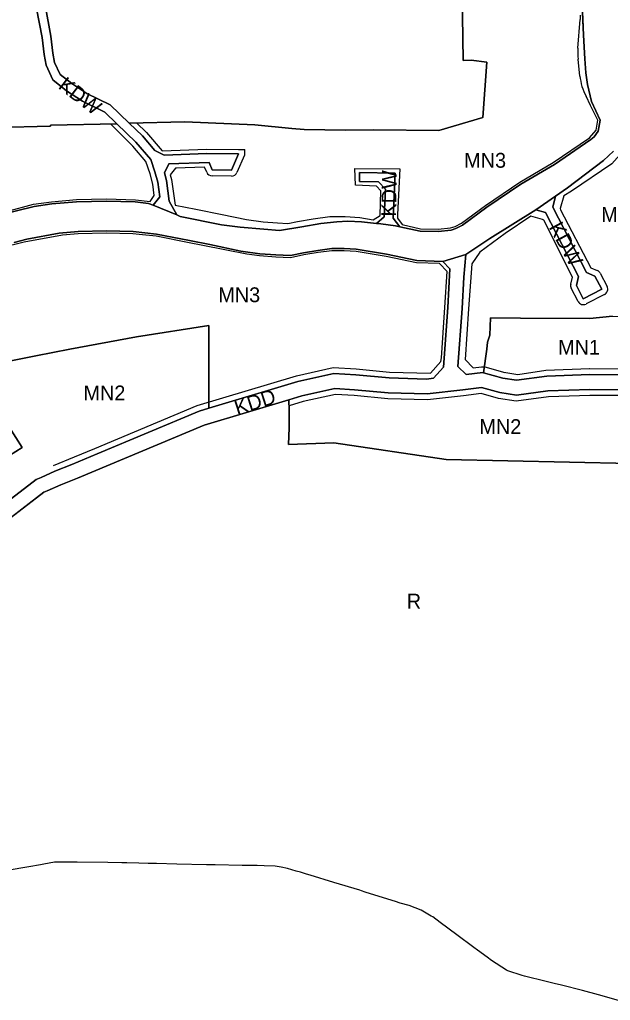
# Model space of a CAD drawing. Extents: x 7417187 to 7419415, y 5539178 to 5540826.
# Drawn here: x 7417830 to 7418229, y 5539345 to 5540006 of the extents above; entities that cross this region are included whole.
import ezdxf

# ---------------------------------------------------------------- set-up
doc = ezdxf.new("R2010")
doc.units = 0
for name, color, linetype in [('linie_rozgraniczajace', 7, 'Continuous'), ('linie_zabudowy_nieprzekraczalne', 7, 'Continuous'), ('oznaczenia_przeznaczen', 7, 'Continuous')]:
    doc.layers.add(name, color=color, linetype=linetype)

msp = doc.modelspace()

# ---------------------------------------------------------------- linework, layer by layer
at = {"layer": 'linie_rozgraniczajace'}
for p, q in [((7418210.59, 5539995.36), (7418209.09, 5540027.1)), ((7417841.94, 5540013.34), (7417845.64, 5539993.82)), ((7417845.64, 5539993.82), (7417846.97, 5539982.25)), ((7418211.34, 5539979.47), (7418210.59, 5539995.36)), ((7417846.97, 5539982.25), (7417848.33, 5539975.12)), ((7418212.06, 5539969.99), (7418211.34, 5539979.47)), ((7417848.33, 5539975.12), (7417852.9, 5539965.11)), ((7418213.25, 5539962.01), (7418212.06, 5539969.99)), ((7417852.9, 5539965.11), (7417862.11, 5539957.8)), ((7418215.88, 5539950.72), (7418213.25, 5539962.01)), ((7417862.11, 5539957.8), (7417872.83, 5539950.87)), ((7417872.83, 5539950.87), (7417887.96, 5539943.47)), ((7418221.87, 5539938.02), (7418215.88, 5539950.72)), ((7417887.96, 5539943.47), (7417896.06, 5539935.67)), ((7417810.61, 5539933.08), (7417851.22, 5539934.03)), ((7417851.22, 5539934.03), (7417810.61, 5539933.08)), ((7417851.18, 5539934.74), (7417896.06, 5539935.67)), ((7417896.06, 5539935.67), (7417851.18, 5539934.74)), ((7417851.22, 5539934.03), (7417851.18, 5539934.74)), ((7417851.18, 5539934.74), (7417851.22, 5539934.03)), ((7417896.06, 5539935.67), (7417908.89, 5539923.32)), ((7418220.53, 5539930.56), (7418221.87, 5539938.02)), ((7418215.47, 5539925.07), (7418217.77, 5539926.8)), ((7418217.77, 5539926.8), (7418220.53, 5539930.56)), ((7417908.89, 5539923.32), (7417918.86, 5539911.61)), ((7418190.95, 5539908.26), (7418215.47, 5539925.07)), ((7418230.77, 5539917.17), (7418223.92, 5539910.78)), ((7417918.86, 5539911.61), (7417921.67, 5539903.35)), ((7418168.34, 5539894.94), (7418190.95, 5539908.26)), ((7418223.92, 5539910.78), (7418199.71, 5539892.43)), ((7417921.67, 5539903.35), (7417923.53, 5539896.24)), ((7417923.53, 5539896.24), (7417924.87, 5539886.44)), ((7418145.38, 5539879.33), (7418168.34, 5539894.94)), ((7417924.87, 5539886.44), (7417920.45, 5539880.67)), ((7418191.59, 5539886.77), (7418178.38, 5539877.62)), ((7418199.71, 5539892.43), (7418191.59, 5539886.77)), ((7417840.17, 5539879.93), (7417802.91, 5539870.7)), ((7417802.91, 5539870.7), (7417840.17, 5539879.93)), ((7417852.11, 5539881.6), (7417840.17, 5539879.93)), ((7417840.17, 5539879.93), (7417852.11, 5539881.6)), ((7417868.87, 5539883.03), (7417852.11, 5539881.6)), ((7417852.11, 5539881.6), (7417868.87, 5539883.03)), ((7417889.12, 5539883.48), (7417868.87, 5539883.03)), ((7417868.87, 5539883.03), (7417889.12, 5539883.48)), ((7417908.45, 5539882.94), (7417889.12, 5539883.48)), ((7417889.12, 5539883.48), (7417908.45, 5539882.94)), ((7417917.24, 5539881.98), (7417908.45, 5539882.94)), ((7417908.45, 5539882.94), (7417917.24, 5539881.98)), ((7417920.45, 5539880.67), (7417917.24, 5539881.98)), ((7417917.24, 5539881.98), (7417920.45, 5539880.67)), ((7417920.45, 5539880.67), (7417936.35, 5539874.16)), ((7418129.07, 5539867.36), (7418145.38, 5539879.33)), ((7417936.35, 5539874.16), (7417938.72, 5539873.19)), ((7417938.72, 5539873.19), (7417966.51, 5539867.57)), ((7418178.38, 5539877.62), (7418147.41, 5539858.29)), ((7417966.51, 5539867.57), (7417979.02, 5539865.96)), ((7418005.58, 5539863.75), (7418020.68, 5539866.09)), ((7418020.68, 5539866.09), (7418033.43, 5539868.33)), ((7418033.43, 5539868.33), (7418044.19, 5539869.55)), ((7418044.19, 5539869.55), (7418051.69, 5539870.01)), ((7418051.69, 5539870.01), (7418060.94, 5539869.6)), ((7418060.94, 5539869.6), (7418070.99, 5539868.49)), ((7418070.99, 5539868.49), (7418073.97, 5539868.16)), ((7418073.97, 5539868.16), (7418083.89, 5539866.83)), ((7418083.89, 5539866.83), (7418086.85, 5539866.21)), ((7418086.85, 5539866.21), (7418100.5, 5539863.34)), ((7418124.58, 5539865.09), (7418129.07, 5539867.36)), ((7417857.1, 5539861.95), (7417835.32, 5539857.93)), ((7417869.95, 5539863.05), (7417857.1, 5539861.95)), ((7417889.06, 5539863.47), (7417869.95, 5539863.05)), ((7417906.99, 5539862.97), (7417889.06, 5539863.47)), ((7417922.74, 5539861.35), (7417906.99, 5539862.97)), ((7417945.07, 5539856.9), (7417922.74, 5539861.35)), ((7417979.02, 5539865.96), (7417995.05, 5539864.58)), ((7417995.05, 5539864.58), (7418005.58, 5539863.75)), ((7418100.5, 5539863.34), (7418112.6, 5539863.03)), ((7418112.6, 5539863.03), (7418121.24, 5539863.99)), ((7418121.24, 5539863.99), (7418124.58, 5539865.09)), ((7417835.32, 5539857.93), (7417826.89, 5539855.67)), ((7417958.72, 5539854.27), (7417945.07, 5539856.9)), ((7417979.67, 5539849.86), (7417958.72, 5539854.27)), ((7418147.41, 5539858.29), (7418131.18, 5539847.53)), ((7417992.31, 5539848.05), (7417979.67, 5539849.86)), ((7418003.21, 5539847.35), (7417992.31, 5539848.05)), ((7418012.95, 5539846.9), (7418003.21, 5539847.35)), ((7418021.79, 5539848.71), (7418012.95, 5539846.9)), ((7418031.39, 5539850.33), (7418021.79, 5539848.71)), ((7418040.91, 5539851.55), (7418031.39, 5539850.33)), ((7418049.26, 5539851.57), (7418040.91, 5539851.55)), ((7418057.39, 5539851.07), (7418049.26, 5539851.57)), ((7418077.8, 5539847.67), (7418057.39, 5539851.07)), ((7418098.17, 5539843.4), (7418077.8, 5539847.67)), ((7418131.18, 5539847.53), (7418115.79, 5539842.94)), ((7418115.79, 5539842.94), (7418098.17, 5539843.4)), ((7417954.87, 5539732.61), (7418011.89, 5539749.7)), ((7418011.89, 5539749.7), (7418012.17, 5539742.43)), ((7418012.17, 5539742.43), (7418012.2, 5539730.83)), ((7417869.58, 5539696.91), (7417954.87, 5539732.61)), ((7418012.2, 5539730.83), (7418011.72, 5539719.57)), ((7418011.72, 5539719.57), (7418042.23, 5539720.7)), ((7418042.23, 5539720.7), (7418117.97, 5539709.49)), ((7418117.97, 5539709.49), (7418242.64, 5539706.65)), ((7417858.2, 5539692.46), (7417869.58, 5539696.91)), ((7417846.75, 5539687.32), (7417848.94, 5539688.24)), ((7417848.94, 5539688.24), (7417858.2, 5539692.46)), ((7417810.02, 5539659.15), (7417846.75, 5539687.32)), ((7417846.77, 5539436.79), (7417844.56, 5539436.33)), ((7417853.93, 5539438.26), (7417846.77, 5539436.79)), ((7417866.11, 5539438.22), (7417853.93, 5539438.26)), ((7417869.17, 5539438.17), (7417866.11, 5539438.22)), ((7417889.97, 5539437.85), (7417869.17, 5539438.17)), ((7417899.27, 5539437.7), (7417889.97, 5539437.85)), ((7417902.78, 5539437.63), (7417899.27, 5539437.7)), ((7417910.78, 5539437.47), (7417902.78, 5539437.63)), ((7417917.14, 5539437.34), (7417910.78, 5539437.47)), ((7417922.8, 5539437.23), (7417917.14, 5539437.34)), ((7417936.55, 5539436.91), (7417922.8, 5539437.23)), ((7417956.45, 5539436.46), (7417936.55, 5539436.91)), ((7417835.28, 5539434.72), (7417823.32, 5539432.65)), ((7417836.64, 5539434.96), (7417835.28, 5539434.72)), ((7417844.56, 5539436.33), (7417836.64, 5539434.96)), ((7417962.17, 5539436.33), (7417956.45, 5539436.46)), ((7417980.49, 5539436.01), (7417962.17, 5539436.33)), ((7417989.19, 5539435.85), (7417980.49, 5539436.01)), ((7417990.59, 5539435.82), (7417989.19, 5539435.85)), ((7417995.25, 5539435.73), (7417990.59, 5539435.82)), ((7418002.69, 5539435.5), (7417995.25, 5539435.73)), ((7418006.65, 5539434.7), (7418002.69, 5539435.5)), ((7418010.93, 5539433.83), (7418006.65, 5539434.7)), ((7418016.85, 5539432.18), (7418010.93, 5539433.83)), ((7418019.77, 5539431.37), (7418016.85, 5539432.18)), ((7418023.93, 5539430.1), (7418019.77, 5539431.37)), ((7418026.23, 5539429.4), (7418023.93, 5539430.1)), ((7418042.16, 5539424.55), (7418026.23, 5539429.4)), ((7418059.77, 5539419.19), (7418042.16, 5539424.55)), ((7418060.83, 5539418.87), (7418059.77, 5539419.19)), ((7418063.4, 5539418.05), (7418060.83, 5539418.87)), ((7418075.83, 5539414.1), (7418063.4, 5539418.05)), ((7418083.78, 5539411.57), (7418075.83, 5539414.1)), ((7418087.03, 5539410.64), (7418083.78, 5539411.57)), ((7418093.11, 5539408.89), (7418087.03, 5539410.64)), ((7418101.11, 5539405.89), (7418093.11, 5539408.89)), ((7418107.79, 5539401.88), (7418101.11, 5539405.89)), ((7418108.88, 5539401.24), (7418107.79, 5539401.88)), ((7418114.02, 5539397.42), (7418108.88, 5539401.24)), ((7418125.14, 5539389.19), (7418114.02, 5539397.42)), ((7418136.55, 5539380.72), (7418125.14, 5539389.19)), ((7418138.99, 5539378.92), (7418136.55, 5539380.72)), ((7418145.62, 5539374.05), (7418138.99, 5539378.92)), ((7418148.55, 5539371.9), (7418145.62, 5539374.05)), ((7418158.55, 5539365.49), (7418148.55, 5539371.9)), ((7418159.45, 5539364.92), (7418158.55, 5539365.49)), ((7418169.25, 5539361.73), (7418159.45, 5539364.92)), ((7418170.74, 5539361.25), (7418169.25, 5539361.73)), ((7418185.41, 5539357.7), (7418170.74, 5539361.25)), ((7418190.69, 5539356.41), (7418185.41, 5539357.7)), ((7418195.67, 5539355.2), (7418190.69, 5539356.41)), ((7418209.75, 5539351.6), (7418195.67, 5539355.2)), ((7418220.7, 5539348.79), (7418209.75, 5539351.6)), ((7418234.1, 5539345.03), (7418220.7, 5539348.79))]:
    msp.add_line(p, q, dxfattribs=at)
for points in [[(7418127.97, 5540068.95), (7418129.52, 5539978.31), (7418134.9, 5539978.47), (7418145.39, 5539977.11), (7418142.73, 5539939.87), (7418112.93, 5539931.04), (7418069.19, 5539931.47), (7418050.22, 5539931.25), (7418022.22, 5539931.87), (7418013.86, 5539932.53), (7417989.02, 5539934.87), (7417941.84, 5539936.98), (7417904.27, 5539936.1), (7417891.45, 5539948.45), (7417875.79, 5539956.1), (7417865.61, 5539962.68), (7417857.76, 5539968.91), (7417854.09, 5539976.95), (7417852.9, 5539983.16), (7417851.57, 5539994.72), (7417847.64, 5540015.5)], [(7418209.09, 5540027.1), (7418210.59, 5539995.36), (7418211.34, 5539979.47), (7418212.06, 5539969.99), (7418213.25, 5539962.01), (7418215.88, 5539950.72), (7418221.87, 5539938.02), (7418220.53, 5539930.56), (7418217.77, 5539926.8), (7418215.47, 5539925.07), (7418190.95, 5539908.26), (7418168.34, 5539894.94), (7418145.38, 5539879.33), (7418129.07, 5539867.36), (7418124.58, 5539865.09), (7418121.24, 5539863.99), (7418112.6, 5539863.03), (7418100.5, 5539863.34), (7418086.85, 5539866.21), (7418082.15, 5539872.08), (7418083.53, 5539902.42), (7418059.61, 5539902.82), (7418059.55, 5539896.82), (7418072.26, 5539896.61), (7418077.03, 5539891.53), (7418076.18, 5539872.89), (7418070.99, 5539868.49), (7418060.94, 5539869.6), (7418051.69, 5539870.01), (7418044.19, 5539869.55), (7418033.43, 5539868.33), (7418020.68, 5539866.09), (7418005.58, 5539863.75), (7417995.05, 5539864.58), (7417979.02, 5539865.96), (7417966.51, 5539867.57), (7417938.72, 5539873.19), (7417936.35, 5539874.16), (7417931.32, 5539883.51), (7417929.43, 5539897.41), (7417928.09, 5539902.52), (7417931.04, 5539908.52), (7417958.15, 5539909.55), (7417960.27, 5539904.53), (7417973.27, 5539904.39), (7417977.95, 5539915.34), (7417956.75, 5539915.57), (7417927.86, 5539914.39), (7417921.67, 5539917.57), (7417913.27, 5539927.43), (7417904.27, 5539936.1), (7417941.84, 5539936.98), (7417989.02, 5539934.87), (7418013.86, 5539932.53), (7418022.22, 5539931.87), (7418050.22, 5539931.25), (7418069.19, 5539931.47), (7418112.93, 5539931.04), (7418142.73, 5539939.87), (7418145.39, 5539977.11), (7418134.9, 5539978.47), (7418129.52, 5539978.31), (7418127.97, 5540068.95)], [(7417847.64, 5540015.5), (7417851.57, 5539994.72), (7417852.9, 5539983.16), (7417854.09, 5539976.95), (7417857.76, 5539968.91), (7417865.61, 5539962.68), (7417875.79, 5539956.1), (7417891.45, 5539948.45), (7417904.27, 5539936.1), (7417913.27, 5539927.43), (7417921.67, 5539917.57), (7417927.86, 5539914.39), (7417956.75, 5539915.57), (7417977.95, 5539915.34), (7417973.27, 5539904.39), (7417960.27, 5539904.53), (7417958.15, 5539909.55), (7417931.04, 5539908.52), (7417928.09, 5539902.52), (7417929.43, 5539897.41), (7417931.32, 5539883.51), (7417936.35, 5539874.16), (7417920.45, 5539880.67), (7417924.87, 5539886.44), (7417923.53, 5539896.24), (7417921.67, 5539903.35), (7417918.86, 5539911.61), (7417908.89, 5539923.32), (7417896.06, 5539935.67), (7417887.96, 5539943.47), (7417872.83, 5539950.87), (7417862.11, 5539957.8), (7417852.9, 5539965.11), (7417848.33, 5539975.12), (7417846.97, 5539982.25), (7417845.64, 5539993.82), (7417841.94, 5540013.34)], [(7418230.03, 5539805.96), (7418214.86, 5539804.35), (7418168.02, 5539804.71), (7418147.8, 5539804.87), (7418147.31, 5539793.29), (7418145.8, 5539788.38), (7418145.28, 5539783.81), (7418143.19, 5539767.85), (7418142.61, 5539768.01), (7418131.41, 5539766.71), (7418125.86, 5539772.01), (7418128.65, 5539811.13), (7418129.77, 5539832.22), (7418131.18, 5539847.53), (7418147.41, 5539858.29), (7418178.38, 5539877.62), (7418184.91, 5539875.82), (7418207.22, 5539832.63), (7418205.82, 5539826.64), (7418210.41, 5539817.75), (7418222.84, 5539824.18), (7418218.26, 5539833.06), (7418212.55, 5539835.39), (7418189.78, 5539879.47), (7418191.59, 5539886.77), (7418199.71, 5539892.43), (7418223.92, 5539910.78), (7418230.77, 5539917.17)], [(7417826.89, 5539855.67), (7417835.32, 5539857.93), (7417857.1, 5539861.95), (7417869.95, 5539863.05), (7417889.06, 5539863.47), (7417906.99, 5539862.97), (7417922.74, 5539861.35), (7417945.07, 5539856.9), (7417958.72, 5539854.27), (7417979.67, 5539849.86), (7417992.31, 5539848.05), (7418003.21, 5539847.35), (7418012.95, 5539846.9), (7418021.79, 5539848.71), (7418031.39, 5539850.33), (7418040.91, 5539851.55), (7418049.26, 5539851.57), (7418057.39, 5539851.07), (7418077.8, 5539847.67), (7418098.17, 5539843.4), (7418115.79, 5539842.94), (7418120.53, 5539837.82), (7418119.15, 5539811.73), (7418116.72, 5539777.78), (7418116.07, 5539771.74), (7418109.53, 5539764.18), (7418104.74, 5539763.64), (7418079.51, 5539764.37), (7418056.99, 5539766.44), (7418042.23, 5539767.31), (7418018.07, 5539761.99), (7417958.11, 5539744.02), (7417958.03, 5539799.71), (7417909.36, 5539792.17), (7417864.21, 5539783.76), (7417841.36, 5539779.19), (7417801.05, 5539771.12)], [(7417804.28, 5539667.35), (7417841.69, 5539696.04), (7417844.93, 5539697.4), (7417854.3, 5539701.67), (7417865.77, 5539706.15), (7417882.67, 5539713.25), (7417951.49, 5539742.04), (7417958.11, 5539744.02), (7418018.07, 5539761.99), (7418042.23, 5539767.31), (7418056.99, 5539766.44), (7418079.51, 5539764.37), (7418104.74, 5539763.64), (7418109.53, 5539764.18), (7418116.07, 5539771.74), (7418116.72, 5539777.78), (7418119.15, 5539811.73), (7418120.53, 5539837.82), (7418115.79, 5539842.94), (7418131.18, 5539847.53), (7418129.77, 5539832.22), (7418128.65, 5539811.13), (7418125.86, 5539772.01), (7418131.41, 5539766.71), (7418142.61, 5539768.01), (7418143.19, 5539767.85), (7418156.27, 5539764.29), (7418165.41, 5539762.82), (7418185.74, 5539765.64), (7418214.71, 5539766.66), (7418240.54, 5539766.43)], [(7417801.05, 5539771.12), (7417841.36, 5539779.19), (7417864.21, 5539783.76), (7417909.36, 5539792.17), (7417958.03, 5539799.71), (7417958.11, 5539744.02), (7417951.49, 5539742.04), (7417882.67, 5539713.25), (7417865.77, 5539706.15), (7417854.3, 5539701.67), (7417844.93, 5539697.4), (7417841.69, 5539696.04), (7417804.28, 5539667.35)], [(7418240.01, 5539756.43), (7418214.84, 5539756.66), (7418186.6, 5539755.66), (7418165.3, 5539752.71), (7418154.16, 5539754.5), (7418141.85, 5539757.86), (7418129.13, 5539756.37), (7418105.15, 5539753.62), (7418078.91, 5539754.39), (7418056.24, 5539756.46), (7418043.03, 5539757.25), (7418020.58, 5539752.31), (7418011.89, 5539749.7), (7417954.87, 5539732.61), (7417869.58, 5539696.91), (7417858.2, 5539692.46), (7417848.94, 5539688.24), (7417846.75, 5539687.32), (7417810.02, 5539659.15)], [(7417823.66, 5539731.08), (7417832.22, 5539717.46), (7417823.75, 5539712.14)], [(7417823.75, 5539712.14), (7417832.22, 5539717.46), (7417823.66, 5539731.08)]]:
    msp.add_lwpolyline(points, dxfattribs=at)
for points in [[(7418086.85, 5539866.21), (7418083.89, 5539866.83), (7418073.97, 5539868.16), (7418070.99, 5539868.49), (7418076.18, 5539872.89), (7418077.03, 5539891.53), (7418072.26, 5539896.61), (7418059.55, 5539896.82), (7418059.61, 5539902.82), (7418083.53, 5539902.42), (7418082.15, 5539872.08)], [(7418178.38, 5539877.62), (7418191.59, 5539886.77), (7418189.78, 5539879.47), (7418212.55, 5539835.39), (7418218.26, 5539833.06), (7418222.84, 5539824.18), (7418210.41, 5539817.75), (7418205.82, 5539826.64), (7418207.22, 5539832.63), (7418184.91, 5539875.82)], [(7418143.19, 5539767.85), (7418145.28, 5539783.81), (7418145.8, 5539788.38), (7418147.31, 5539793.29), (7418147.8, 5539804.87), (7418168.02, 5539804.71), (7418214.86, 5539804.35), (7418230.03, 5539805.96), (7418234.36, 5539805.67), (7418241.45, 5539808.76), (7418252.53, 5539812.06), (7418261.32, 5539812.68), (7418261.19, 5539812.28), (7418255.59, 5539791.7), (7418252.73, 5539782.38), (7418249.79, 5539769.47), (7418245.72, 5539765.92), (7418240.54, 5539766.43), (7418214.71, 5539766.66), (7418185.74, 5539765.64), (7418165.41, 5539762.82), (7418156.27, 5539764.29)], [(7418287.08, 5539743.57), (7418290.72, 5539737.09), (7418284.43, 5539700.08), (7418242.64, 5539706.65), (7418117.97, 5539709.49), (7418042.23, 5539720.7), (7418011.72, 5539719.57), (7418012.2, 5539730.83), (7418012.17, 5539742.43), (7418011.89, 5539749.7), (7418020.58, 5539752.31), (7418043.03, 5539757.25), (7418056.24, 5539756.46), (7418078.91, 5539754.39), (7418105.15, 5539753.62), (7418129.13, 5539756.37), (7418141.85, 5539757.86), (7418154.16, 5539754.5), (7418165.3, 5539752.71), (7418186.6, 5539755.66), (7418214.84, 5539756.66), (7418240.01, 5539756.43), (7418251.75, 5539755.28), (7418272.38, 5539748.77)]]:
    msp.add_lwpolyline(points, close=True, dxfattribs=at)
at = {"layer": 'linie_zabudowy_nieprzekraczalne'}
for points in [[(7418206.76, 5539986.46), (7418208.4, 5540005.79)], [(7418208.08, 5539967.79), (7418206.85, 5539979.11)], [(7418215.23, 5539948.01), (7418212.23, 5539954.21)], [(7418220.21, 5539938.1), (7418215.23, 5539948.01)], [(7417918.49, 5539883.26), (7417921.22, 5539887.33), (7417920.2, 5539894.86), (7417918.45, 5539901.84), (7417915.65, 5539910.1), (7417906.76, 5539920.44), (7417891.82, 5539935.48)], [(7417909.22, 5539936.22), (7417915.93, 5539929.69), (7417926.61, 5539917.28)], [(7418088.23, 5539867.83), (7418100.67, 5539864.84), (7418112.54, 5539864.53), (7418120.92, 5539865.46), (7418124.01, 5539866.48), (7418128.29, 5539868.64), (7418144.51, 5539880.56), (7418167.54, 5539896.21), (7418190.15, 5539909.52), (7418214.49, 5539926.21), (7418219.14, 5539931.25), (7418220.21, 5539938.1)], [(7417926.61, 5539917.28), (7417956.71, 5539918.57), (7417977.98, 5539918.34)], [(7417981.96, 5539914.54), (7417976.95, 5539902.82)], [(7417977.98, 5539918.34), (7417982.33, 5539918.36)], [(7417982, 5539918.37), (7417981.96, 5539914.54)], [(7418237.01, 5539916.28), (7418235.12, 5539914.66), (7418229.63, 5539908.71), (7418202.5, 5539890.11), (7418197.31, 5539887.05)], [(7417955.11, 5539906.49), (7417935.53, 5539905.66)], [(7417956.59, 5539902.97), (7417955.11, 5539906.49)], [(7417935.53, 5539905.66), (7417932.04, 5539901.18)], [(7417932.04, 5539901.18), (7417932.87, 5539898.04), (7417935.4, 5539880.75)], [(7417935.53, 5539905.66), (7417935.64, 5539905.23)], [(7417973.23, 5539900.39), (7417960.23, 5539900.53)], [(7418056.8, 5539894.34), (7418056.5, 5539905.49)], [(7418056.5, 5539905.49), (7418086.67, 5539905.35), (7418085.27, 5539874.56), (7418085.11, 5539871.98)], [(7418073.42, 5539873.88), (7418073.97, 5539890.4), (7418070.96, 5539893.62), (7418056.8, 5539894.34)], [(7418197.31, 5539887.05), (7418194.78, 5539878.52)], [(7417742.82, 5539863.31), (7417751.84, 5539862.66), (7417763.01, 5539863.59), (7417780.48, 5539867.12), (7417802.58, 5539872.16), (7417821.71, 5539876.55), (7417839.88, 5539881.41), (7417851.94, 5539883.09), (7417868.79, 5539884.53), (7417889.13, 5539884.98), (7417908.56, 5539884.44), (7417918.49, 5539883.26)], [(7417935.4, 5539880.75), (7417949.25, 5539877.99), (7417966.96, 5539874.5), (7417983.41, 5539871.04), (7417994.52, 5539869.46), (7418004.4, 5539868.82), (7418011.27, 5539868.5), (7418017.84, 5539869.85), (7418028.23, 5539871.6), (7418039.52, 5539873.05), (7418049.91, 5539873.07), (7418059.83, 5539872.46), (7418068.83, 5539870.85)], [(7418068.83, 5539870.85), (7418073.42, 5539873.88)], [(7418174.95, 5539873.44), (7418157.79, 5539861.77), (7418140.57, 5539849.13)], [(7418182.8, 5539871.15), (7418174.95, 5539873.44)], [(7418194.78, 5539878.52), (7418195.03, 5539877.65)], [(7418195.03, 5539877.65), (7418215.4, 5539838.55)], [(7418085.11, 5539871.98), (7418088.28, 5539867.84)], [(7418183.83, 5539870.63), (7418182.8, 5539871.15)], [(7418203.02, 5539832.23), (7418183.83, 5539870.63)], [(7417859.28, 5539860.63), (7417833.56, 5539855.91)], [(7417953.89, 5539853.63), (7417944.78, 5539855.43), (7417922.53, 5539859.87), (7417911.07, 5539860.98), (7417906.88, 5539861.48), (7417889.06, 5539861.98), (7417870.03, 5539861.56), (7417859.28, 5539860.63)], [(7417833.56, 5539855.91), (7417827.25, 5539854.22), (7417807.7, 5539849.74), (7417785.31, 5539844.63), (7417766.25, 5539840.79), (7417758.79, 5539840.16)], [(7417983.58, 5539847.79), (7417953.89, 5539853.63)], [(7418113.47, 5539841.5), (7418098, 5539841.9), (7418077.52, 5539846.2), (7418057.23, 5539849.58), (7418049.22, 5539850.07), (7418041.01, 5539850.06), (7418031.61, 5539848.85), (7418022.06, 5539847.24), (7418013.08, 5539845.4), (7418003.13, 5539845.86), (7417992.16, 5539846.56), (7417983.58, 5539847.79)], [(7418140.56, 5539849.13), (7418135.26, 5539841.19)], [(7418118.69, 5539836.19), (7418113.47, 5539841.5)], [(7418135.26, 5539841.19), (7418133.12, 5539810.83), (7418130.69, 5539776.78)], [(7418114.46, 5539775.39), (7418114.73, 5539777.94), (7418117.15, 5539811.91), (7418118.69, 5539836.19)], [(7418215.4, 5539838.55), (7418219.77, 5539836.77)], [(7418221.81, 5539834.9), (7418226.4, 5539826.01)], [(7418201.93, 5539827.55), (7418203.02, 5539832.23)], [(7418206.86, 5539815.92), (7418202.27, 5539824.8)], [(7418224.68, 5539820.62), (7418212.25, 5539814.2)], [(7418107.5, 5539767.56), (7418114.46, 5539775.39)], [(7418130.69, 5539776.78), (7418136.14, 5539771.29)], [(7417867.48, 5539711.21), (7417881.13, 5539716.94), (7417950.15, 5539745.81), (7418017.07, 5539765.87), (7418041.92, 5539771.34), (7418057.29, 5539770.43), (7418079.76, 5539768.37), (7418107.5, 5539767.56)], [(7418136.14, 5539771.29), (7418141.77, 5539771.94)], [(7418141.77, 5539771.94), (7418144.04, 5539771.77)], [(7418144.04, 5539771.77), (7418157.43, 5539768.12)], [(7418156.81, 5539768.26), (7418166.35, 5539766.72)], [(7418166.27, 5539766.76), (7418185.09, 5539769.59)], [(7418185.09, 5539769.59), (7418214.53, 5539770.65)], [(7418214.79, 5539770.66), (7418243.78, 5539770.47)], [(7418282.26, 5539741.04), (7418271.11, 5539744.98), (7418250.95, 5539751.35), (7418239.8, 5539752.44), (7418214.89, 5539752.66), (7418186.95, 5539751.68), (7418165.26, 5539748.66), (7418153.31, 5539750.59), (7418141.55, 5539753.8), (7418129.6, 5539752.4)], [(7418111.42, 5539750.31), (7418105.33, 5539749.62), (7418078.67, 5539750.39), (7418055.94, 5539752.48), (7418043.35, 5539753.22), (7418021.59, 5539748.43), (7418012.05, 5539745.57)], [(7418129.59, 5539752.4), (7418111.43, 5539750.31)], [(7417853.25, 5539705.4), (7417867.46, 5539711.28)]]:
    msp.add_lwpolyline(points, dxfattribs=at)
for centre, radius, start, end in [((7418187.32, 5540007.68), 21.17, 354.87604, 2.76158), ((7418245.18, 5539983.26), 38.55, 175.23944, 186.16557), ((7418246.04, 5539971.97), 38.19, 186.27965, 207.70629), ((7417960.29, 5539904.55), 4.02, 203.16622, 269.16354), ((7417973.28, 5539904.38), 3.99, 269.33593, 336.97129), ((7418218.3, 5539833.12), 3.94, 26.90672, 68.07238), ((7418205.77, 5539826.63), 3.95, 166.49609, 207.60006), ((7418222.86, 5539824.17), 3.99, 297.19282, 27.41043), ((7418210.41, 5539817.73), 3.99, 207.08762, 297.51563)]:
    msp.add_arc(centre, radius, start, end, dxfattribs=at)

# ---------------------------------------------------------------- texts
at = {"layer": 'oznaczenia_przeznaczen'}
for s, rotation, p in [('KDW', 322.49073, (7417855.9, 5539959.94)), ('KDW', 89.10469, (7418084.23, 5539873)), ('KDW', 298.53228, (7418186.94, 5539866.01)), ('KDD', 17.77911, (7417977.16, 5539739.15))]:
    msp.add_text(s, height=10, rotation=rotation, dxfattribs=at).set_placement(p)
for s, p in [('MN3', (7418130.11, 5539906.01)), ('MN3', (7418222.49, 5539869.47)), ('MN3', (7417964.37, 5539815.41)), ('MN1', (7418193.43, 5539780.04)), ('MN2', (7417873.51, 5539749.27)), ('MN2', (7418140.37, 5539726.61)), ('R', (7418091.39, 5539609.01))]:
    msp.add_text(s, height=10, dxfattribs=at).set_placement(p)

doc.saveas('drawing.dxf')
